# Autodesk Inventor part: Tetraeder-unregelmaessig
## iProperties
Created: 2004-12
Part Number: Tetraeder-unregelmaessig
Material: .
Document SubType Name: Modeling
Designer: rsc
Manufacturer: Standard
Standards Organization: Custom
Kanten: brechen
Oberflächen: Ra 3,2
Radien: 2
Toleranzen: ISO 2768 - m
Author: rsc
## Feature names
1. Sweeping1
